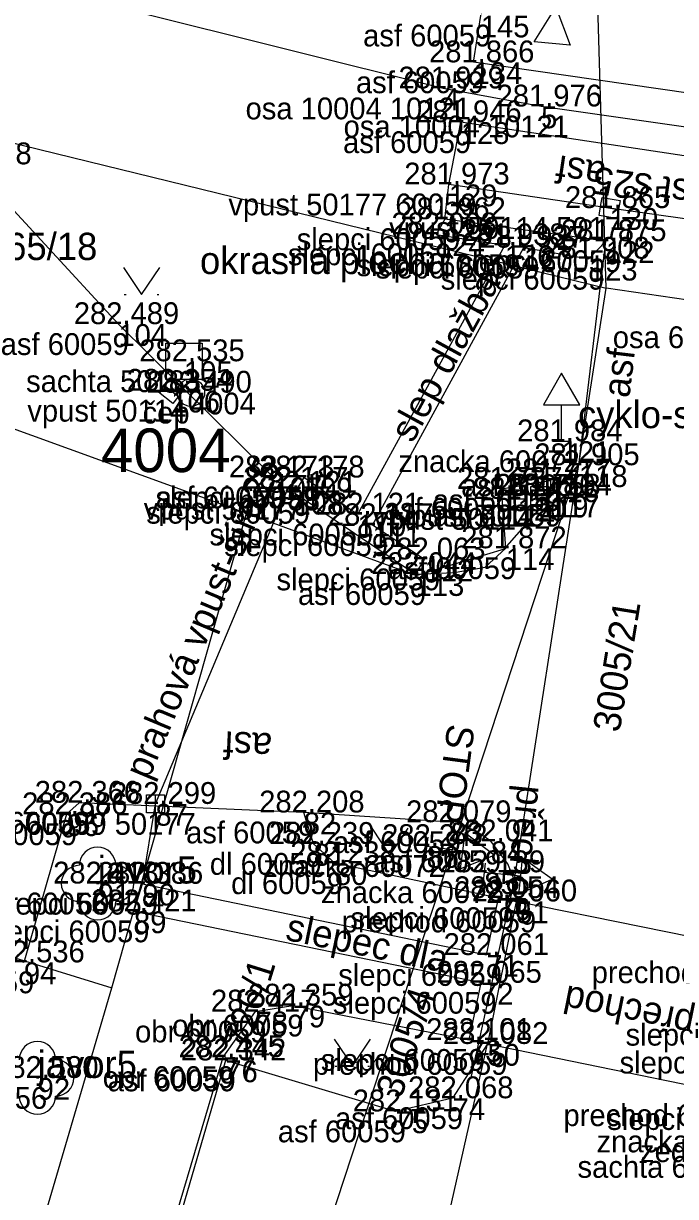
# Model space of a CAD drawing. Extents: x -728659 to -728362, y -1073110 to -1072943.
# Drawn here: x -728525.94 to -728507.99, y -1073071.85 to -1073039.57 of the extents above; entities that cross this region are included whole.
import ezdxf

# ---------------------------------------------------------------- set-up
doc = ezdxf.new("R2010")
doc.units = 0
for name, color, linetype in [('Vrstva 1', 7, 'Continuous'), ('Vrstva 4', 7, 'Continuous'), ('Vrstva 43', 7, 'Continuous'), ('Vrstva 47', 7, 'Continuous'), ('Vrstva 50', 7, 'Continuous'), ('Vrstva 51', 7, 'Continuous'), ('Vrstva 53', 7, 'Continuous'), ('Vrstva 55', 7, 'Continuous'), ('Vrstva 57', 7, 'Continuous'), ('Vrstva 58', 7, 'Continuous'), ('Vrstva 60', 7, 'Continuous'), ('Vrstva 61', 7, 'Continuous'), ('Vrstva 62', 7, 'Continuous'), ('Vrstva 63', 7, 'Continuous')]:
    doc.layers.add(name, color=color, linetype=linetype)

msp = doc.modelspace()

# ---------------------------------------------------------------- linework, layer by layer
at = {"layer": 'Vrstva 1'}
msp.add_lwpolyline([(-728462.112, -1073044.292), (-728486.957, -1073044.611), (-728498.776, -1073043.699), (-728511.695, -1073041.857), (-728514.393, -1073041.361), (-728535.912, -1073035.983), (-728560.369, -1073026.548)], dxfattribs=at)
at = {"layer": 'Vrstva 4'}
for points in [[(-728511.114, -1073037.394), (-728511.286, -1073039.124), (-728510.894, -1073040.171), (-728511.888, -1073040.075), (-728511.286, -1073039.124)], [(-728498.776, -1073043.699), (-728511.695, -1073041.857), (-728514.393, -1073041.361)]]:
    msp.add_lwpolyline(points, dxfattribs=at)
at = {"layer": 'Vrstva 43'}
msp.add_line((-728522.31, -1073061.049), (-728518.67, -1073052.375), dxfattribs=at)
for points in [[(-728499.778, -1073046.077), (-728509.811, -1073044.652), (-728514.235, -1073044.003)], [(-728510.057, -1073044.609), (-728510.015, -1073044.363), (-728509.522, -1073044.448), (-728509.607, -1073044.941), (-728510.1, -1073044.856), (-728510.057, -1073044.609), (-728509.565, -1073044.695)], [(-728522.068, -1073049.523), (-728521.912, -1073049.328), (-728521.522, -1073049.64), (-728521.834, -1073050.03), (-728522.224, -1073049.718), (-728522.068, -1073049.523), (-728521.678, -1073049.835)], [(-728512.594, -1073052.656), (-728512.594, -1073052.406), (-728512.094, -1073052.406), (-728512.094, -1073052.906), (-728512.594, -1073052.906), (-728512.594, -1073052.656), (-728512.094, -1073052.656)], [(-728511.98, -1073052.567), (-728511.98, -1073052.317), (-728511.48, -1073052.317), (-728511.48, -1073052.817), (-728511.98, -1073052.817), (-728511.98, -1073052.567), (-728511.48, -1073052.567)], [(-728522.31, -1073061.299), (-728522.56, -1073061.299), (-728522.56, -1073060.799), (-728522.06, -1073060.799), (-728522.06, -1073061.299), (-728522.31, -1073061.299), (-728522.31, -1073060.799)]]:
    msp.add_lwpolyline(points, dxfattribs=at)
at = {"layer": 'Vrstva 47'}
msp.add_lwpolyline([(-728522.025, -1073048.368), (-728521.025, -1073048.368), (-728521.025, -1073049.368), (-728522.025, -1073049.368), (-728522.025, -1073048.368)], dxfattribs=at)
at = {"layer": 'Vrstva 50'}
for p, q in [((-728523.932, -1073063.24), (-728523.861, -1073063.24)), ((-728525.586, -1073068.59), (-728525.515, -1073068.59))]:
    msp.add_line(p, q, dxfattribs=at)
for centre, start, end in [((-728523.902, -1073062.739), 0, 180), ((-728524.402, -1073063.239), 90, 270), ((-728523.402, -1073063.239), 270, 90), ((-728523.902, -1073063.739), 180, 0), ((-728525.557, -1073068.089), 0, 180), ((-728525.057, -1073068.589), 270, 90), ((-728525.557, -1073069.089), 180, 0)]:
    msp.add_arc(centre, 0.5, start, end, dxfattribs=at)
at = {"layer": 'Vrstva 51'}
for p, q in [((-728499.558, -1073044.443), (-728513.906, -1073042.29)), ((-728511.38, -1073051.07), (-728510.88, -1073051.07)), ((-728522.668, -1073063.246), (-728522.31, -1073061.049)), ((-728514.814, -1073061.961), (-728514.88, -1073062.457)), ((-728513.234, -1073062.681), (-728513.286, -1073063.179))]:
    msp.add_line(p, q, dxfattribs=at)
for points in [[(-728513.553, -1073040.642), (-728513.354, -1073039.355), (-728513.463, -1073034.501), (-728513.865, -1073029.238)], [(-728496.482, -1073035.776), (-728497.494, -1073036.644), (-728498.316, -1073037.996), (-728498.528, -1073038.603), (-728498.459, -1073039.486), (-728498.149, -1073040.128), (-728497.533, -1073040.603), (-728496.825, -1073040.892), (-728494.827, -1073041.079), (-728486.835, -1073041.479), (-728486.937, -1073042.858), (-728494.923, -1073042.391), (-728498.977, -1073042.014), (-728499.069, -1073042.727), (-728513.553, -1073040.642)], [(-728514.343, -1073044.959), (-728514.235, -1073044.003), (-728513.906, -1073042.29)], [(-728519.061, -1073052.066), (-728523.329, -1073047.846), (-728527.39, -1073043.448), (-728532.404, -1073042.69)], [(-728515.148, -1073054.725), (-728514.9, -1073054.321), (-728516.336, -1073053.379), (-728512.168, -1073045.742), (-728510.38, -1073046.047), (-728509.916, -1073045.565), (-728514.343, -1073044.959), (-728514.586, -1073045.376), (-728512.695, -1073045.676), (-728516.744, -1073053.086), (-728518.227, -1073052.067), (-728518.483, -1073052.487), (-728515.148, -1073054.725)], [(-728515.148, -1073054.725), (-728514.086, -1073054.679), (-728513.239, -1073054.536), (-728512.667, -1073054.014), (-728512.785, -1073052.379), (-728511.438, -1073052.146), (-728511.426, -1073052.561), (-728510.655, -1073051.729), (-728509.916, -1073045.565)], [(-728511.13, -1073051.07), (-728511.13, -1073050.07), (-728510.63, -1073050.07), (-728511.13, -1073049.195), (-728511.63, -1073050.07), (-728511.13, -1073050.07)], [(-728512.38, -1073063.734), (-728512.393, -1073063.245), (-728512.614, -1073062.698), (-728513.079, -1073062.079), (-728513.527, -1073061.773), (-728514.184, -1073061.553), (-728518.227, -1073061.285), (-728524.406, -1073061.017), (-728524.753, -1073061.334), (-728525.929, -1073065.41), (-728532.201, -1073063.347)], [(-728512.865, -1073063.643), (-728517.37, -1073062.681), (-728517.956, -1073062.15), (-728518.227, -1073061.285)], [(-728514.847, -1073062.209), (-728513.856, -1073062.341), (-728513.922, -1073062.836), (-728512.988, -1073062.456), (-728513.79, -1073061.845), (-728513.856, -1073062.341)], [(-728513.26, -1073062.93), (-728512.265, -1073063.032), (-728512.316, -1073063.53), (-728511.395, -1073063.122), (-728512.214, -1073062.535), (-728512.265, -1073063.032)], [(-728513.171, -1073067.654), (-728513.679, -1073067.545), (-728513.348, -1073065.972), (-728522.9, -1073064.007), (-728522.668, -1073063.246), (-728513.2, -1073065.207), (-728512.865, -1073063.643), (-728512.38, -1073063.734)], [(-728505.498, -1073065.132), (-728512.38, -1073063.734), (-728513.171, -1073067.654), (-728506.273, -1073069.065), (-728505.498, -1073065.132)], [(-728531.131, -1073104.759), (-728528.363, -1073095.064), (-728524.847, -1073082.829), (-728520.445, -1073068.019), (-728519.555, -1073066.763), (-728518.532, -1073066.599), (-728513.679, -1073067.545)], [(-728513.171, -1073067.654), (-728514.129, -1073069.149), (-728515.701, -1073069.511), (-728520.385, -1073068.108), (-728525.367, -1073085.199), (-728528.271, -1073095.025), (-728524.268, -1073096.199), (-728523.716, -1073096.605), (-728523.622, -1073097.442)], [(-728524.69, -1073104.648), (-728518.127, -1073087.402), (-728515.708, -1073078.91), (-728513.171, -1073067.654)]]:
    msp.add_lwpolyline(points, dxfattribs=at)
at = {"layer": 'Vrstva 53'}
msp.add_lwpolyline([(-728658.89, -1072943.19), (-728655.13, -1072951.34), (-728641.33, -1072971.93), (-728620.02, -1072997.18), (-728600.31, -1073011.5), (-728598.74, -1073012.6), (-728581.66, -1073022.5), (-728572.55, -1073027.78), (-728541.12, -1073039.22), (-728509.9, -1073046.86), (-728510.22, -1073036.28), (-728510.71, -1073032.54), (-728543.86, -1073026.9), (-728564.68, -1073020.02), (-728582.13, -1073004.22), (-728604.14, -1072988.92), (-728619.81, -1072972.56), (-728640.48, -1072947.72)], dxfattribs=at)
at = {"layer": 'Vrstva 55'}
for p, q in [((-728502.6, -1073047.92), (-728509.9, -1073046.86)), ((-728525.44, -1073096.73), (-728510.66, -1073051.71)), ((-728531.77, -1073094.25), (-728523.51, -1073066.11))]:
    msp.add_line(p, q, dxfattribs=at)
for points in [[(-728549.3, -1073042.35), (-728519.8, -1073053.05), (-728515.13, -1073054.76), (-728512.7, -1073054.03), (-728510.66, -1073051.71), (-728509.9, -1073046.86)], [(-728513.61, -1073068.54), (-728512.45, -1073063.25), (-728510.66, -1073051.71)], [(-728551.4, -1073057.49), (-728537.29, -1073061.85), (-728523.51, -1073066.11), (-728519.8, -1073053.05)]]:
    msp.add_lwpolyline(points, dxfattribs=at)
at = {"layer": 'Vrstva 58'}
for p, q in [((-728523.166, -1073047.035), (-728523.116, -1073047.035)), ((-728522.266, -1073047.035), (-728522.216, -1073047.035)), ((-728516.329, -1073062.466), (-728516.279, -1073062.466)), ((-728515.429, -1073062.466), (-728515.379, -1073062.466)), ((-728517.364, -1073068.269), (-728517.314, -1073068.269)), ((-728516.464, -1073068.269), (-728516.414, -1073068.269))]:
    msp.add_line(p, q, dxfattribs=at)
for points in [[(-728523.191, -1073046.285), (-728522.691, -1073047.035), (-728522.191, -1073046.285)], [(-728516.354, -1073061.716), (-728515.854, -1073062.466), (-728515.354, -1073061.716)], [(-728517.389, -1073067.519), (-728516.889, -1073068.269), (-728516.389, -1073067.519)]]:
    msp.add_lwpolyline(points, dxfattribs=at)
at = {"layer": 'Vrstva 60'}
for p, q in [((-728513.553, -1073040.642), (-728513.553, -1073040.642)), ((-728514.393, -1073041.361), (-728514.393, -1073041.361)), ((-728511.695, -1073041.857), (-728511.695, -1073041.857)), ((-728513.906, -1073042.29), (-728513.906, -1073042.29)), ((-728514.235, -1073044.003), (-728514.235, -1073044.003)), ((-728509.811, -1073044.652), (-728509.811, -1073044.652)), ((-728514.343, -1073044.959), (-728514.343, -1073044.959)), ((-728514.586, -1073045.376), (-728514.586, -1073045.376)), ((-728512.695, -1073045.676), (-728512.695, -1073045.676)), ((-728512.168, -1073045.742), (-728512.168, -1073045.742)), ((-728509.916, -1073045.565), (-728509.916, -1073045.565)), ((-728510.38, -1073046.047), (-728510.38, -1073046.047)), ((-728523.329, -1073047.846), (-728523.329, -1073047.846)), ((-728521.525, -1073048.868), (-728521.525, -1073048.868)), ((-728521.873, -1073049.679), (-728521.873, -1073049.679)), ((-728521.333, -1073049.732), (-728521.333, -1073049.732)), ((-728511.13, -1073051.07), (-728511.13, -1073051.07)), ((-728510.655, -1073051.729), (-728510.655, -1073051.729)), ((-728519.061, -1073052.066), (-728519.061, -1073052.066)), ((-728518.227, -1073052.067), (-728518.227, -1073052.067)), ((-728511.438, -1073052.146), (-728511.438, -1073052.146)), ((-728518.67, -1073052.375), (-728518.67, -1073052.375)), ((-728518.483, -1073052.487), (-728518.483, -1073052.487)), ((-728512.785, -1073052.379), (-728512.785, -1073052.379)), ((-728511.73, -1073052.567), (-728511.73, -1073052.567)), ((-728511.426, -1073052.561), (-728511.426, -1073052.561)), ((-728512.344, -1073052.656), (-728512.344, -1073052.656)), ((-728516.744, -1073053.086), (-728516.744, -1073053.086)), ((-728516.336, -1073053.379), (-728516.336, -1073053.379)), ((-728512.667, -1073054.014), (-728512.667, -1073054.014)), ((-728514.9, -1073054.321), (-728514.9, -1073054.321)), ((-728515.148, -1073054.725), (-728515.148, -1073054.725)), ((-728524.406, -1073061.017), (-728524.406, -1073061.017)), ((-728522.31, -1073061.049), (-728522.31, -1073061.049)), ((-728518.227, -1073061.285), (-728518.227, -1073061.285)), ((-728524.753, -1073061.334), (-728524.753, -1073061.334)), ((-728514.184, -1073061.553), (-728514.184, -1073061.553)), ((-728517.956, -1073062.15), (-728517.956, -1073062.15)), ((-728514.847, -1073062.209), (-728514.847, -1073062.209)), ((-728513.079, -1073062.079), (-728513.079, -1073062.079)), ((-728517.37, -1073062.681), (-728517.37, -1073062.681)), ((-728513.26, -1073062.93), (-728513.26, -1073062.93)), ((-728523.897, -1073063.24), (-728523.897, -1073063.24)), ((-728522.668, -1073063.246), (-728522.668, -1073063.246)), ((-728512.865, -1073063.643), (-728512.865, -1073063.643)), ((-728512.38, -1073063.734), (-728512.38, -1073063.734)), ((-728522.9, -1073064.007), (-728522.9, -1073064.007)), ((-728525.929, -1073065.41), (-728525.929, -1073065.41)), ((-728513.2, -1073065.207), (-728513.2, -1073065.207)), ((-728513.348, -1073065.972), (-728513.348, -1073065.972)), ((-728519.555, -1073066.763), (-728519.555, -1073066.763)), ((-728518.532, -1073066.599), (-728518.532, -1073066.599)), ((-728513.679, -1073067.545), (-728513.679, -1073067.545)), ((-728513.171, -1073067.654), (-728513.171, -1073067.654)), ((-728520.445, -1073068.019), (-728520.445, -1073068.019)), ((-728520.385, -1073068.108), (-728520.385, -1073068.108)), ((-728525.551, -1073068.59), (-728525.551, -1073068.59)), ((-728514.129, -1073069.149), (-728514.129, -1073069.149)), ((-728515.701, -1073069.511), (-728515.701, -1073069.511))]:
    msp.add_line(p, q, dxfattribs=at)
at = {"layer": 'Vrstva 63'}
msp.add_line((-728521.358, -1073049.732), (-728521.308, -1073049.732), dxfattribs=at)
msp.add_circle((-728521.333, -1073049.732), 0.378, dxfattribs=at)

# ---------------------------------------------------------------- texts
at = {"layer": 'Vrstva 43'}
for s, rotation, p in [('prahova vpust š25', 171.9163, (-728502.097, -1073044.659)), ('prahová vpust-šíře25', 67.2349, (-728522.496, -1073060.417))]:
    msp.add_text(s, height=0.75, rotation=rotation, dxfattribs=at).set_placement(p)
at = {"layer": 'Vrstva 51'}
for s, rotation, p in [('asf', 171.4661, (-728509.894, -1073043.391)), ('slep dlažba', 61.3759, (-728515.232, -1073051.144)), ('asf', 83.1635, (-728509.267, -1073049.895)), ('asf', 177.5165, (-728519.083, -1073059.108)), ('slepec dla', 348.2984, (-728518.759, -1073064.785)), ('přechod', 168.5173, (-728507.432, -1073066.758))]:
    msp.add_text(s, height=0.75, rotation=rotation, dxfattribs=at).set_placement(p)
at = {"layer": 'Vrstva 57'}
msp.add_text('3065/18', height=0.75, dxfattribs=at).set_placement((-728527.534, -1073046.083))
for s, rotation, p in [('3005/21', 80.7822, (-728509.535, -1073059.105)), ('726/1', 72.7479, (-728519.74, -1073067.857)), ('3005/4', 71.9724, (-728515.548, -1073069.187))]:
    msp.add_text(s, height=0.75, rotation=rotation, dxfattribs=at).set_placement(p)
at = {"layer": 'Vrstva 60'}
for s, p in [('145', (-728513.354, -1073039.955)), ('134', (-728513.553, -1073041.242)), ('4', (-728514.393, -1073041.961)), ('5', (-728511.695, -1073042.457)), ('128', (-728513.906, -1073042.89)), ('129', (-728514.235, -1073044.603)), ('130', (-728509.811, -1073045.252)), ('125', (-728514.343, -1073045.559)), ('124', (-728514.586, -1073045.976)), ('126', (-728512.695, -1073046.276)), ('127', (-728512.168, -1073046.342)), ('122', (-728509.916, -1073046.165)), ('123', (-728510.38, -1073046.647)), ('104', (-728523.329, -1073048.446)), ('105', (-728521.525, -1073049.468)), ('106', (-728521.873, -1073050.279)), ('4004', (-728521.333, -1073050.332)), ('121', (-728511.13, -1073051.67)), ('118', (-728510.655, -1073052.329)), ('107', (-728519.061, -1073052.666)), ('109', (-728518.227, -1073052.667)), ('116', (-728511.438, -1073052.746)), ('88', (-728518.67, -1073052.975)), ('108', (-728518.483, -1073053.087)), ('115', (-728512.785, -1073052.979)), ('119', (-728511.73, -1073053.167)), ('117', (-728511.426, -1073053.161)), ('120', (-728512.344, -1073053.256)), ('110', (-728516.744, -1073053.686)), ('111', (-728516.336, -1073053.979)), ('114', (-728512.667, -1073054.614)), ('112', (-728514.9, -1073054.921)), ('113', (-728515.148, -1073055.325)), ('97', (-728524.406, -1073061.617)), ('87', (-728522.31, -1073061.649)), ('82', (-728518.227, -1073061.885)), ('96', (-728524.753, -1073061.934)), ('83', (-728514.184, -1073062.153)), ('81', (-728517.956, -1073062.75)), ('86', (-728514.847, -1073062.809)), ('84', (-728513.079, -1073062.679)), ('80', (-728517.37, -1073063.281)), ('85', (-728513.26, -1073063.53)), ('91', (-728523.897, -1073063.84)), ('90', (-728522.668, -1073063.846)), ('70', (-728512.865, -1073064.243)), ('51', (-728512.38, -1073064.334)), ('89', (-728522.9, -1073064.607)), ('94', (-728525.929, -1073066.01)), ('71', (-728513.2, -1073065.807)), ('72', (-728513.348, -1073066.572)), ('78', (-728519.555, -1073067.363)), ('79', (-728518.532, -1073067.199)), ('73', (-728513.679, -1073068.145)), ('50', (-728513.171, -1073068.254)), ('77', (-728520.445, -1073068.619)), ('76', (-728520.385, -1073068.708)), ('92', (-728525.551, -1073069.19)), ('74', (-728514.129, -1073069.749)), ('75', (-728515.701, -1073070.111))]:
    msp.add_text(s, height=0.6, dxfattribs=at).set_placement(p)
at = {"layer": 'Vrstva 61'}
for s, p in [('281.866', (-728514.779, -1073040.642)), ('281.929', (-728515.62, -1073041.361)), ('281.976', (-728512.921, -1073041.857)), ('281.946', (-728515.132, -1073042.29)), ('283.078', (-728528.617, -1073043.448)), ('281.973', (-728515.461, -1073044.003)), ('281.865', (-728511.039, -1073044.652)), ('281.962', (-728515.567, -1073044.959)), ('282.008', (-728515.813, -1073045.376)), ('281.938', (-728513.922, -1073045.676)), ('281.927', (-728513.394, -1073045.742)), ('281.875', (-728511.144, -1073045.565)), ('281.908', (-728511.607, -1073046.047)), ('282.489', (-728524.556, -1073047.846)), ('282.535', (-728522.753, -1073048.868)), ('282.354', (-728523.098, -1073049.679)), ('282.490', (-728522.558, -1073049.732)), ('281.984', (-728512.355, -1073051.07)), ('281.905', (-728511.883, -1073051.729)), ('282.173', (-728520.287, -1073052.066)), ('282.178', (-728519.454, -1073052.067)), ('281.777', (-728512.664, -1073052.146)), ('282.117', (-728519.896, -1073052.375)), ('282.121', (-728519.662, -1073052.487)), ('281.737', (-728514.011, -1073052.379)), ('281.742', (-728513.568, -1073052.656)), ('281.758', (-728512.957, -1073052.567)), ('281.804', (-728512.651, -1073052.561)), ('282.121', (-728517.923, -1073053.086)), ('282.117', (-728517.562, -1073053.379)), ('281.872', (-728513.891, -1073054.014)), ('282.063', (-728516.126, -1073054.321)), ('282.044', (-728516.373, -1073054.725)), ('282.366', (-728525.632, -1073061.017)), ('282.299', (-728523.537, -1073061.049)), ('282.386', (-728525.979, -1073061.334)), ('282.208', (-728519.454, -1073061.285)), ('282.079', (-728515.411, -1073061.553)), ('282.239', (-728519.183, -1073062.15)), ('282.242', (-728516.071, -1073062.209)), ('282.041', (-728514.258, -1073062.079)), ('282.238', (-728518.597, -1073062.681)), ('282.139', (-728514.487, -1073062.93)), ('282.418', (-728525.124, -1073063.24)), ('282.386', (-728523.894, -1073063.246)), ('282.054', (-728514.09, -1073063.643)), ('282.060', (-728513.605, -1073063.734)), ('282.421', (-728524.079, -1073064.007)), ('282.536', (-728527.155, -1073065.41)), ('282.061', (-728514.379, -1073065.207)), ('282.065', (-728514.576, -1073065.972)), ('282.359', (-728519.759, -1073066.599)), ('282.417', (-728520.781, -1073066.763)), ('282.101', (-728514.858, -1073067.545)), ('282.082', (-728514.395, -1073067.654)), ('282.445', (-728521.673, -1073068.019)), ('282.342', (-728521.609, -1073068.108)), ('282.580', (-728526.776, -1073068.59)), ('282.068', (-728515.356, -1073069.149)), ('282.131', (-728516.88, -1073069.511))]:
    msp.add_text(s, height=0.6, dxfattribs=at).set_placement(p)
at = {"layer": 'Vrstva 62'}
for s, p in [('asf 60059', (-728516.593, -1073040.205)), ('asf 60059', (-728516.792, -1073041.492)), ('osa 10004 10121', (-728519.829, -1073042.211)), ('osa 10004 10121', (-728517.131, -1073042.707)), ('asf 60059', (-728517.145, -1073043.14)), ('vpust 50177 60059', (-728520.302, -1073044.853)), ('vpust 50114 50177', (-728515.877, -1073045.502)), ('slepci 60059', (-728518.421, -1073045.809)), ('slepci 60059', (-728518.664, -1073046.226)), ('slepci 60059', (-728513.994, -1073046.415)), ('slepci 60059', (-728516.773, -1073046.526)), ('slepci 60059', (-728516.246, -1073046.592)), ('slepci 60059', (-728514.458, -1073046.897)), ('osa 60082', (-728509.721, -1073048.507)), ('asf 60059', (-728526.568, -1073048.696)), ('sachta 50183', (-728525.87, -1073049.718)), ('vpust 50114', (-728525.835, -1073050.529)), ('čep', (-728522.663, -1073050.582)), ('znacka 60072', (-728515.624, -1073051.92)), ('asf 60059', (-728513.894, -1073052.579)), ('slepci 60059', (-728522.305, -1073052.917)), ('asf 60059', (-728522.3, -1073052.916)), ('asf 60059', (-728514.677, -1073052.996)), ('vpust 50177', (-728522.633, -1073053.225)), ('slepci 60059', (-728522.561, -1073053.337)), ('asf 60059', (-728516.024, -1073053.229)), ('vpust 50114', (-728515.692, -1073053.417)), ('asf 60059', (-728514.665, -1073053.411)), ('vpust 50114', (-728516.306, -1073053.506)), ('slepci 60059', (-728520.822, -1073053.936)), ('slepci 60059', (-728520.414, -1073054.229)), ('asf 60059', (-728515.906, -1073054.864)), ('slepci 60059', (-728518.978, -1073055.171)), ('asf 60059', (-728518.387, -1073055.575)), ('asf 60059', (-728527.645, -1073061.867)), ('vpust 50114 60059 50177', (-728530.478, -1073061.899)), ('asf 60059', (-728527.992, -1073062.184)), ('asf 60059', (-728521.466, -1073062.135)), ('asf 60059', (-728517.423, -1073062.403)), ('dl 60059', (-728520.812, -1073063)), ('znacka 60072', (-728519.341, -1073063.059)), ('asf 60059', (-728516.318, -1073062.929)), ('dl 60059', (-728520.226, -1073063.531)), ('znacka 60072', (-728517.754, -1073063.78)), ('str 60056', (-728526.981, -1073064.09)), ('slepci 60059', (-728526.746, -1073064.096)), ('slepci 60059', (-728516.943, -1073064.493)), ('prechod 60059', (-728517.185, -1073064.584)), ('slepci 60059', (-728526.978, -1073064.857)), ('slepci 60059', (-728517.278, -1073066.057)), ('prechod 60059', (-728510.303, -1073065.982)), ('asf 60059', (-728529.168, -1073066.26)), ('slepci 60059', (-728517.426, -1073066.822)), ('obr 60059', (-728522.87, -1073067.613)), ('obr 60059', (-728521.847, -1073067.449)), ('slepci 60059', (-728509.369, -1073067.701)), ('prechod 60059', (-728517.976, -1073068.504)), ('slepci 60059', (-728517.757, -1073068.395)), ('slepci 60059', (-728509.535, -1073068.467)), ('obr 60059', (-728523.76, -1073068.869)), ('asf 60059', (-728523.624, -1073068.958)), ('str 60056', (-728528.635, -1073069.44)), ('prechod 60059', (-728511.078, -1073069.915)), ('asf 60059', (-728517.368, -1073069.999)), ('slepci 60059', (-728509.875, -1073070.021)), ('asf 60059', (-728518.94, -1073070.361)), ('znacka 60072', (-728510.17, -1073070.637)), ('zed 50183', (-728508.973, -1073070.905)), ('sachta 60059', (-728510.693, -1073071.338))]:
    msp.add_text(s, height=0.6, dxfattribs=at).set_placement(p)
at = {"layer": 'Vrstva 63'}
for s, height, p in [('okrasná plocha', 0.75, (-728521.084, -1073046.469)), ('cyklo-stezky', 0.75, (-728510.679, -1073050.709)), ('4004', 1.2, (-728523.811, -1073051.919)), ('javor5', 0.75, (-728523.897, -1073063.24)), ('javor5', 0.75, (-728525.551, -1073068.59))]:
    msp.add_text(s, height=height, dxfattribs=at).set_placement(p)
for s, rotation, p in [('STOP', 262.4365, (-728514.263, -1073058.826)), ('přechod', 264.1378, (-728512.334, -1073060.508))]:
    msp.add_text(s, height=0.75, rotation=rotation, dxfattribs=at).set_placement(p)

doc.saveas('drawing.dxf')
